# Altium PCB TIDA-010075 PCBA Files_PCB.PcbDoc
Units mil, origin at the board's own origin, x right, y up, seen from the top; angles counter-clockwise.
Board outline 1182.08 x 709 mil, 2 copper layers (Top Layer, Bottom Layer), stack 62 mil thick; 32 components, 16 nets, 78 pads, 87 vias.
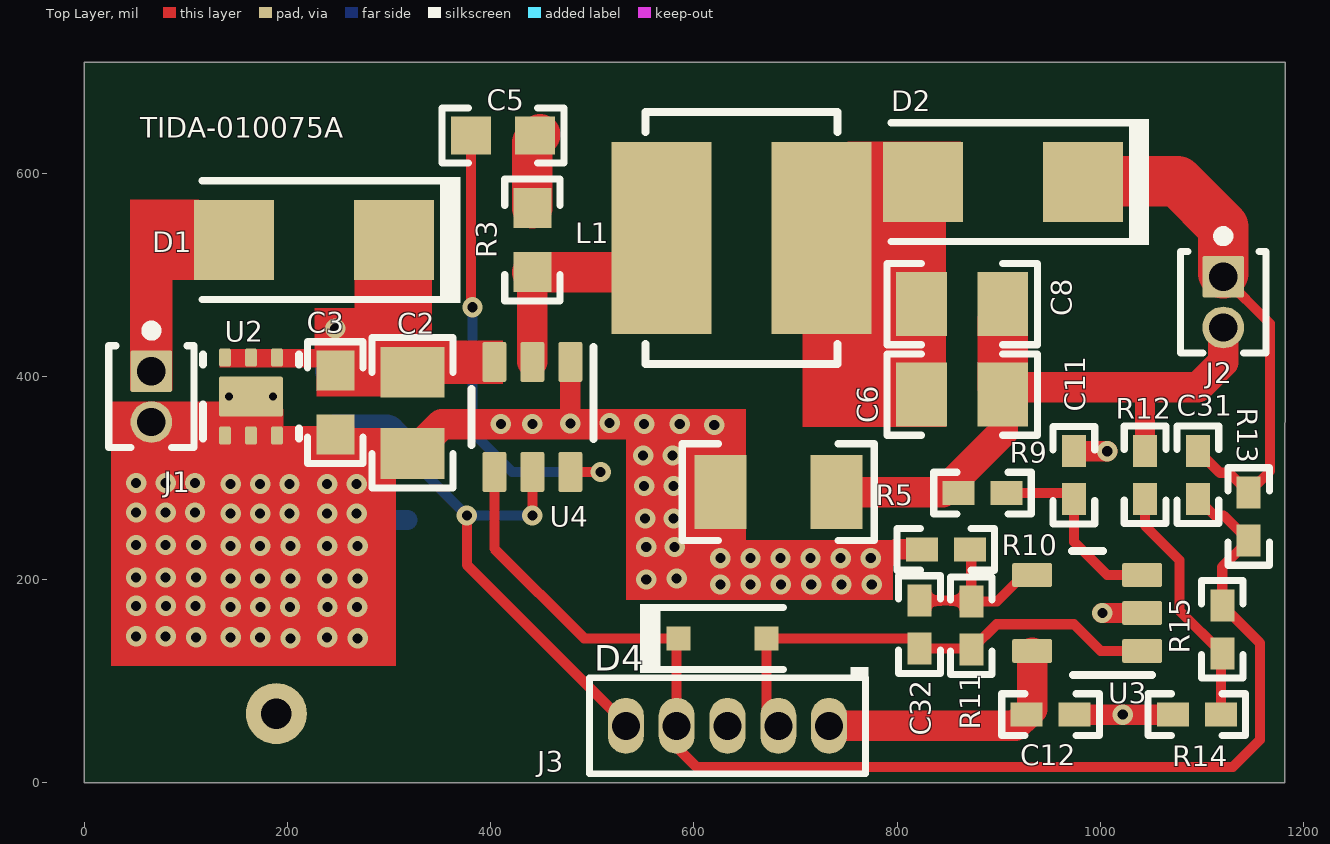
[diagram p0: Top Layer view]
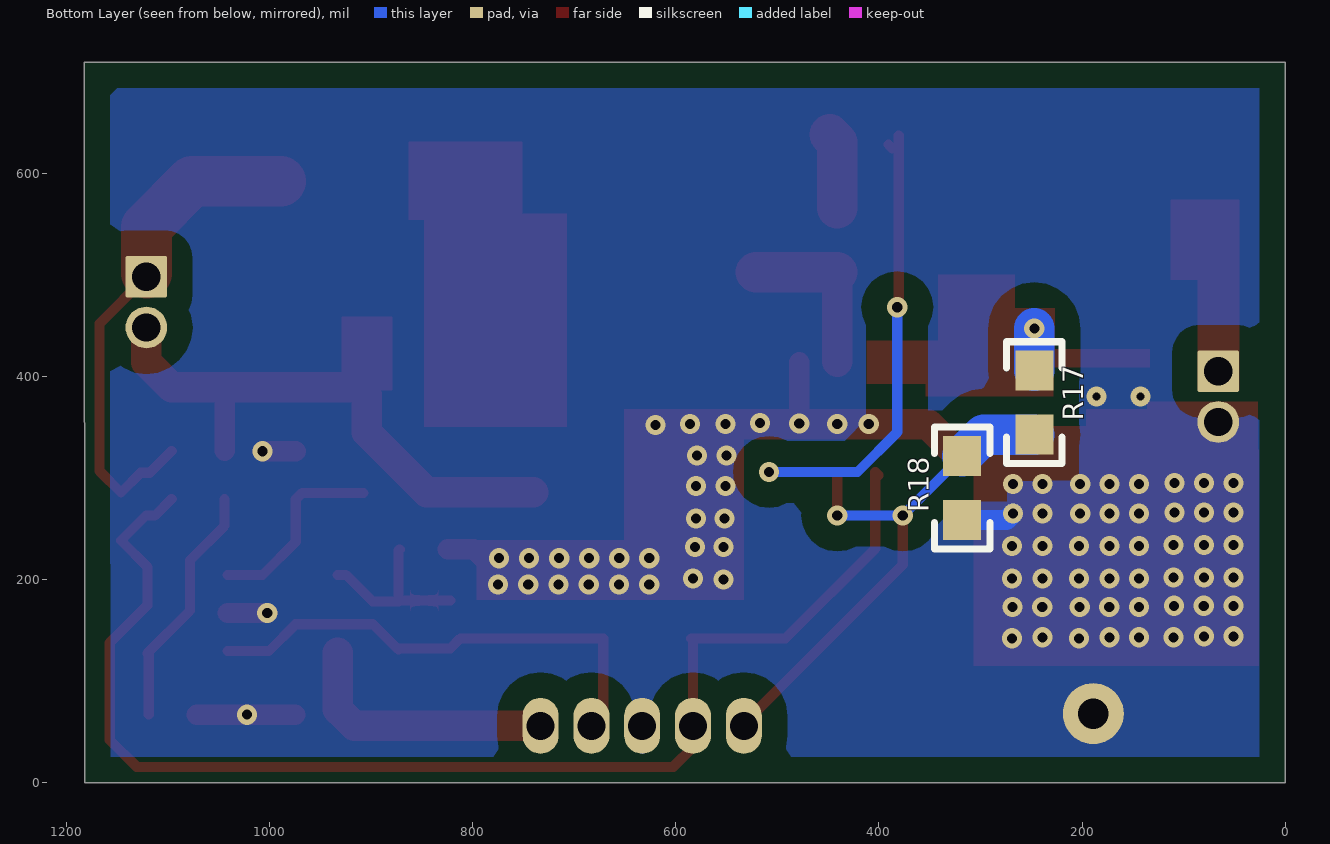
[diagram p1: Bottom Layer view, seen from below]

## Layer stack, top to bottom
Top Solder: solder mask 0.4, Solder Resist, Dk 3.5
Top Layer: signal copper 1.4
Dielectric1: core 59.2, FR-4, Dk 4.8
Bottom Layer: signal copper 1.4
Bottom Solder: solder mask 0.4, Solder Resist, Dk 3.5

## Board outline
0,0 1181.58,0 1182.08,709 0,709

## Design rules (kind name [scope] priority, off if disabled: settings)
AcuteAngle [All] p1: minimum=4.50000000000000E+0001 checktracksonly=FALSE
AssemblyTestPointUsage [All] p1: valid=2
BoardOutlineClearance BoardOutlineClearance_MountingHoles [OnCopper and InComponentClass('Mounting Holes')] p1: gap=40 ignorepadtopadclearanceinfootprint=FALSE
BoardOutlineClearance BoardOutlineClearance_Poly [OnCopper and IsPoly] p2: gap=25 ignorepadtopadclearanceinfootprint=FALSE
BoardOutlineClearance [OnCopper and Not InComponentClass('Logo') and not InComponentClass('FiducialMark') and not InRegion(1000,500,4000,800) and not InPoly] p3: gap=8 ignorepadtopadclearanceinfootprint=FALSE
Clearance Clearance_Keepouts [((IsTrack Or IsArc) And Not InPoly) And IsFree and IsKeepOut vs ((IsTrack Or IsArc) And Not InPoly) And IsFree and IsKeepOut] p1: gap=0 ignorepadtopadclearanceinfootprint=FALSE
Clearance Clearance_Poly [InPolygon] p2: gap=25 ignorepadtopadclearanceinfootprint=FALSE except(0: Arc-Hole Track-Hole SMDPad-Hole THPad-Hole Via-Hole Fill-Hole Poly-Hole Region-Hole Text-Hole)
Clearance Clearance_FiducialMark [IsKeepOut and InComponentClass('FiducialMark') vs IsPad and InComponentClass('FiducialMark')] p3: gap=0 ignorepadtopadclearanceinfootprint=FALSE
Clearance [All] p4: gap=7.87 ignorepadtopadclearanceinfootprint=FALSE except(0: Arc-Hole Track-Hole SMDPad-Hole THPad-Hole Via-Hole Fill-Hole Poly-Hole Region-Hole Text-Hole)
ComponentClearance ComponentClearance_MountingHoles_FiducialMarks [InComponentClass('Mounting Holes') vs InComponentClass('FiducialMark')] p1: gap=50 collisioncheckmode=3 verticalgap=10 showdistances=FALSE
ComponentClearance ComponentClearance_Shunt [InComponentClass('Header') vs InComponentClass('Shunt')] p2: gap=0 collisioncheckmode=3 verticalgap=0 showdistances=FALSE
ComponentClearance ComponentClearance_Logo [InComponentClass('Logo')] p3: gap=50 collisioncheckmode=3 verticalgap=10 showdistances=FALSE
ComponentClearance ComponentClearance_ScrewToNut [(HasFootprint('NY PMS 440 0025 PH')) vs (HasFootprint('Keystone_1902C'))] p4: gap=5 collisioncheckmode=3 verticalgap=10 showdistances=FALSE
ComponentClearance ComponentClearance_MountingHoles [InComponentClass('Mounting Holes')] p5: gap=250 collisioncheckmode=3 verticalgap=100000 showdistances=FALSE
ComponentClearance ComponentClearance_SmallPassives [HasFootprint('0201*') or HasFootprint('0402*') or HasFootprint('0508') or HasFootprint('0603*') or HasFootprint('0612') or HasFootprint('0805*') or HasFootprint('0815*') or HasFootprint('0830*') or HasFootprint('1206*') or HasFootprint('1210*') or HasFootprint('1808*') or HasFootprint('1812*') or HasFootprint('1825*') or HasFootprint('2010*') or HasFootprint('2220*') or HasFootprint('2225*') or HasFootprint('2512*') or HasFootprint('2728*') or HasFootprint('3518*') vs HasFootprint('0201*') or HasFootprint('0402*') or HasFootprint('0508') or HasFootprint('0603*') or HasFootprint('0612') or HasFootprint('0805*') or HasFootprint('0815*') or HasFootprint('0830*') or HasFootprint('1206*') or HasFootprint('1210*') or HasFootprint('1808*') or HasFootprint('1812*') or HasFootprint('1825*') or HasFootprint('2010*') or HasFootprint('2220*') or HasFootprint('2225*') or HasFootprint('2512*') or HasFootprint('2728*') or HasFootprint('3518*')] p6: gap=14.96 collisioncheckmode=3 verticalgap=10 showdistances=FALSE
ComponentClearance ComponentClearance_THtoSMT [IsThruComponent vs IsSMTComponent] p7: gap=10 collisioncheckmode=3 verticalgap=30 showdistances=FALSE
ComponentClearance ComponentClearance_THtoTH [IsThruComponent vs IsThruComponent] p8: gap=30 collisioncheckmode=3 verticalgap=30 showdistances=FALSE
ComponentClearance [All] p9: gap=10 collisioncheckmode=3 verticalgap=10 showdistances=FALSE
DiffPairsRouting [All] p1: maxlimit=100 minlimit=10 mostfreqgap=10 toplayer_minwidth=15 toplayer_maxwidth=15 toplayer_prefwidth=15 bottomlayer_minwidth=15 bottomlayer_maxwidth=15 bottomlayer_prefwidth=15 maxuncoupledlength=1000
FabricationTestPointUsage TestPointUsage [All] p1: valid=2 allowmultiple=FALSE
FabricationTestpoint Testpoint [All] p1: side=3 testpointundercomponent=TRUE minsize=40 maxsize=100 preferedsize=60 minholesize=0 maxholesize=40 preferedholesize=32 testpointgrid=1 allowsidetop=TRUE allowsidebottom=TRUE usegrid=TRUE gridtolerance=0.01
FanoutControl Fanout_LCC [IsLCC] p1: bgadir=Out bgaviamode=Centered fanoutstyle=Auto fanoutdirection=Alternating viagrid=1 // Fanout_LCC (Default Rule)
FanoutControl Fanout_BGA [IsBGA] p2: bgadir=Out bgaviamode=Centered fanoutstyle=Auto fanoutdirection=Alternating viagrid=1 // Fanout_BGA (Default Rule)
FanoutControl Fanout_Default [All] p4: bgadir=Out bgaviamode=Centered fanoutstyle=Auto fanoutdirection=Alternating viagrid=1 // Fanout_Default (Default Rule)
FanoutControl Fanout_Small [(CompPinCount < 5)] p5: bgadir=Out bgaviamode=Centered fanoutstyle=Auto fanoutdirection=OutThenIn viagrid=1 // Fanout_Small (Default Rule)
HoleSize [All] p1: absolutevalues=TRUE maxlimit=251 minlimit=7.87 maxpercent=80.000 minpercent=20.000
MinimumAnnularRing MinimumAnnularRing_ThermalPadVias [IsVia and InAnyComponent] p1: minimumring=5.91
MinimumAnnularRing [All] p2: minimumring=8
MinimumSolderMaskSliver MinimumSolderMaskSliver_Logo [InComponentClass('Logo') vs InComponentClass('Logo')] p1: minsoldermaskwidth=0.7
MinimumSolderMaskSliver [All] p2: minsoldermaskwidth=3.94
PlaneClearance [All] p1: clearance=10
PlaneConnect [All] p1: planeconnectstyle=Direct reliefexpansion=10 reliefentries=4 reliefconductorwidth=10 reliefairgap=10
PolygonConnect [All] p1: connectstyle=Direct reliefconductorwidth=10 reliefentries=4 polygonreliefangle="90 Angle" airgapwidth=10
RoutingVias ThermalPadVias [IsVia and InAnyComponent] p1: holewidth=7.87 width=19.68 viastyle="Through Hole" minholewidth=7.87 minwidth=19.68 maxholewidth=12.99 maxwidth=23.62
RoutingVias [All] p2: holewidth=16 width=34 viastyle="Through Hole" minholewidth=7.87 minwidth=20 maxholewidth=40 maxwidth=65
SilkToBoardRegionClearance [Not ((IsComment or IsDesignator) And (Hide <> 'False')) and not InRegion(1000,500,4000,800)] p1:
SilkToSilkClearance SilkToSilkClearance_Pb-FreeLogo [(HasFootprint('Pb-Free_Overlay_Medium') OR HasFootprint('Pb-Free_Overlay_Small')) vs (HasFootprint('Pb-Free_Overlay_Medium') OR HasFootprint('Pb-Free_Overlay_Small'))] p1: silktosilkclearance=0
SilkToSilkClearance [All] p2: silktosilkclearance=0
SilkToSolderMaskClearance SilkToComponentPadClearance [(IsPad or IsFill or IsRegion) and InAnycomponent] p1: minsilkscreentomaskgap=0 clearancetoexposedcopper=TRUE
SilkToSolderMaskClearance "Silk to Solder Mask Opening" [All] p2: minsilkscreentomaskgap=0 clearancetoexposedcopper=FALSE
SolderMaskExpansion [All] p1: expansion=1.97
Width [All] p1: maxlimit=100 minlimit=6 preferedwidth=10 checkconnectedcopper=TRUE
14 further rules are at their usual default settings.

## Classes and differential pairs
component class "TIDA-010075 PCBA Files_BlankSheet": C2 C3 C5 C6 C8 C11 C12 C31 C32 D1 D2 D4 J1 J2 J3 L1 R3 R5 R9 R10 R11 R12 R13 R14 R15 R17 R18 U2 U3 U4
component class Header: J1 J2 J3
component class Logo: Logo1
component class "TIDA-010075 PCBA Files_EVM_Hardware": Logo1 Logo3

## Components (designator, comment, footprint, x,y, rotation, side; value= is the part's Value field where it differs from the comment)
C2 "GRM21BR6YA106KE43L" 0805_HV 323,364 r270 top value=10uF
C3 "06035C104KAT2A" 0603 247,374 r270 top value=0.1uF
C5 "06035C104KAT2A" 0603 412,637 r180 top value=0.1uF
C6 "C2012X5R1V226M125AC" 0805_HV 864,382 r0 top value=22uF
C8 "C2012X5R1V226M125AC" 0805_HV 864,471 r0 top value=22uF
C11 "GRM155R71C104KA88D" 0402 974,302.63 r90 top value=0.1uF
C12 "GRM155R71C104KA88D" 0402 951,67 r180 top value=0.1uF
C31 "GRM1555C1E560JA01D" 0402 1096,303 r270 top value=56pF
C32 "885012005009" 0402 822,155.63 r90 top value=22pF
D1 "B340LA-13-F" SMA 226,534 r180 top value=40V
D2 "B340LA-13-F" SMA 904,591 r180 top value=40V
D4 "BAT54HT1G" SOD-323 628,142 r0 top value=30V
J1 "GRPB021VWVN-RC" Sullins_GRPB021VWVN-RC 66,380 r270 top
J2 "GRPB021VWVN-RC" Sullins_GRPB021VWVN-RC 1121,473 r270 top
J3 "GRPB051VWVN-RC" Sullins_GRPB051VWVN-RC 633,56 r180 top
L1 "THPC6045MF-220M" THPC6045MF 647,536 r0 top value=22uH
Logo1 "Texas Instruments" TI_Stacked_Overlay_Small 1175,871 r0 top
Logo3 "FCC disclaimer" FCC_disclaimer 2350,3380 r0 top
R3 "MCR03EZPJ000" 0603 441,534 r270 top value=0
R5 "CRM1206-FX-R100ELF" 1206 683,286 r0 top value=0.1
R9 "CRCW04021K50FKED" 0402 884,285 r180 top value=1.50k
R10 "CRCW04021K50FKED" 0402 848,229.63 r0 top value=1.50k
R11 "CRCW040216K5FKED" 0402 873,154.63 r270 top value=16.5k
R12 "CRCW04020000Z0ED" 0402 1044,303 r270 top value=0
R13 "CRCW0402100KFKED" 0402 1146,262 r90 top value=100k
R14 "CRCW04020000Z0ED" 0402 1095,67 r0 top value=0
R15 "CRCW04023K57FKED" 0402 1120,151 r90 top value=3.57k
R17 "CRCW06031K00FKEA" 0603 247,374 r90 bottom value=1.00k
R18 "CRCW06031K00FKEA" 0603 318,290 r90 bottom value=1.00k
U2 "TVS3300DRVR" DRV0006A 164,380 r90 top
U3 "TLV9001IDBVR" DBV0005A_N 987,167 r180 top
U4 "TPS54202HDDCR" DDC0006A_N 441,360 r270 top

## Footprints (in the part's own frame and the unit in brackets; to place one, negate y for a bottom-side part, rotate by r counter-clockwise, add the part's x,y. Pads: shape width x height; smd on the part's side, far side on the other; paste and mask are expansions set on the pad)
0402 [mm] "0402 from SM-752 data"
  rect 0.8x0.6 smd: 1(-0.6,0) 2(0.6,0)
  silkscreen extent -1.22,-0.52 1.22,0.52, body extent -0.55,-0.3 0.55,0.3, height 0.6
0603 [mm] "0603 from SM-752 data"
  rect 1x0.95 smd: 1(-0.8,0) 2(0.8,0)
  silkscreen extent -1.52,-0.69 1.52,0.69, body extent -0.87,-0.47 0.87,0.47, height 1
0805_HV [mil] "0805 with 30mil clearance between pads"
  rect 50x63 smd: 1(-40,0) 2(40,0)
  silkscreen extent -74,-40 74,40, body extent -43,-29 43,29, height 57
1206 [mm] "1206 from SM-752 data"
  rect 1.3x1.85 smd: 1(-1.45,0) 2(1.45,0)
  silkscreen extent -2.4,-1.21 2.4,1.21, body extent -1.7,-0.9 1.7,0.9, height 1.35
DBV0005A_N [mm] "SOT23, 5-Leads, Body 2.9x1.6mm, Pitch 0.95mm, Lead Span 2.8mm, IPC Medium Density"
  rrect17% 1x0.6 smd: 1(-1.375,0.95) 2(-1.375,0) 3(-1.375,-0.95) 4(1.375,-0.95) 5(1.375,0.95)
  silkscreen extent -1.63,-1.55 0.38,1.55, body extent -1.42,-1.46 1.42,1.46, height 1.09
DDC0006A_N [mm]
  rrect17% 1x0.6 smd: 1(-1.375,0.95) 2(-1.375,0) 3(-1.375,-0.95) 4(1.375,-0.95) 5(1.375,0) 6(1.375,0.95)
  silkscreen extent -1.75,-1.52 0.7,1.53, body extent -1.43,-1.48 1.43,1.49, height 0.92
DRV0006A [mm] "SON, 6-Leads, Body 2x2mm, Pitch 0.65mm, Thermal Pad 1.6x1mm, TI Recommended"
  rrect33% 0.45x0.3 smd: 1(-0.975,0.65) 2(-0.975,0) 3(-0.975,-0.65) 4(0.975,-0.65) 5(0.975,0) 6(0.975,0.65)
  rrect14% 1x0.7 on Top Paste: 7(0,0.45) 7(0,-0.45)
  rrect10% 1x1.6 smd paste-0.5: 7(0,0)
  silkscreen extent -1.05,-1.2 1.05,1.2, body extent -1.05,-1.05 1.05,1.05, height 0.81
FCC_disclaimer [mil]
SMA [mm] "Molded Diode, 2-Leads, Body 4.3x2.6mm, IPC Medium Density, based on OnSemi component dimensions and land pattern"
  rect 2x2 smd: 1(-2,0) 2(2,0)
  silkscreen extent -3.66,-1.57 2.79,1.57, body extent -2.6,-1.3 2.6,1.3, height 2.42
SOD-323 [mm] "NXP recommended land pattern"
  rect 0.6x0.6 smd paste-0.05: 1(-1.1,0) 2(1.1,0)
  silkscreen extent -2.06,-0.86 1.53,0.86, body extent -1.3,-0.67 1.3,0.68, height 1.1
Sullins_GRPB021VWVN-RC [mil] "Sullins"
  rrect10% 41x41 hole 28: 1(-25,0)
  round 41 hole 28: 2(25,0)
  silkscreen extent -70,-42 50,42, body extent -50,-42 50,42, height 157
Sullins_GRPB051VWVN-RC [mm] "SULLINS"
  oval 0.9x1.4 hole 0.7: 1(-2.54,0) 2(-1.27,0) 3(0,0) 4(1.27,0) 5(2.54,0)
  silkscreen extent -3.52,-1.47 3.45,1.2, body extent -3.42,-1.17 3.42,1.17, height 4.2
THPC6045MF [mm] "SMD, 2-Leads, Body 6x6mm"
  rect 2.5x4.8 smd: 1(-2,0) 2(2,0)
  silkscreen extent -2.4,-3.15 2.4,3.15, body extent -3.15,-3.15 3.15,3.15, height 4.5
TI_Stacked_Overlay_Small [mil]
  silkscreen extent -418,-98 418,98

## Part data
C2: "CAP, CERM, 10 µF, 35 V,+/- 10%, X5R, 0805", Cap_Case=0805, Manufacturer=MuRata, Supplier Part Number 1=490-10514-1-ND, TempCo=X5R, Tolerance_%=10, Value2=35V, ValueDisplayed=10µF
C3 C5: "CAP, CERM, 0.1 µF, 50 V,+/- 10%, X7R, 0603", Cap_Case=0603, Manufacturer=AVX, Supplier Part Number 1=478-5052-1-ND, TempCo=X7R, Tolerance_%=10, Value2=50V, ValueDisplayed=0.1µF
C6 C8: "CAP, CERM, 22 µF, 35 V,+/- 20%, X5R, 0805", Cap_Case=0805, Manufacturer=TDK, Supplier Part Number 1=445-14428-1-ND, TempCo=X5R, Tolerance_%=20, Value1="0.00205 ohm", Value2=35V, ValueDisplayed=22µF
C11 C12: "CAP, CERM, 0.1 µF, 16 V,+/- 10%, X7R, 0402", Cap_Case=0402, Manufacturer=MuRata, Supplier Part Number 1=490-3261-1-ND, TempCo=X7R, Tolerance_%=10, Value2=16V, ValueDisplayed=0.1µF
C31: "CAP, CERM, 56 pF, 25 V,+/- 5%, C0G/NP0, 0402", Cap_Case=0402, Manufacturer=MuRata, TempCo=C0G/NP0, Tolerance_%=5, Value2=25V, ValueDisplayed=56pF
C32: "CAP, CERM, 22 pF, 10 V,+/- 5%, C0G/NP0, 0402", Cap_Case=0402, Manufacturer="Wurth Elektronik", Supplier Part Number 1=732-7427-1-ND, TempCo=C0G/NP0, Tolerance_%=5, Value2=10V, ValueDisplayed=DNP
D1 D2: library part CMP-0028413-2, "Diode, Schottky, 40 V, 3 A, SMA", Manufacturer="Diodes Inc.", Value1=3A, Value2=0.45V
D4: library part CMP-0028455-2, "Diode, Schottky, 30 V, 0.2 A, SOD-323", Manufacturer="ON Semiconductor", Value1=0.2A, Value2=0.35V
J1 J2: "Header, 50mil, 2x1, Gold, TH", Manufacturer="Sullins Connector Solutions", Supplier Part Number 1=S9014E-02-ND
J3: "Header, 50mil, 5x1, Gold, TH", Manufacturer="Sullins Connector Solutions", Supplier Part Number 1=S9014E-05-ND
L1: "Inductor, Ferrite, 22 µH, 1.9 A, 0.096 ohm, SMD", Manufacturer=Tai-Tech, Value1="0.096 ohm", Value2=1.9A, ValueDisplayed=22µH
Logo1: library part CMP-0074838-1, "Texas Instrument Corporate Signature"
Logo3: library part CMP-0074847-1, "FCC_disclaimer"
R3: library part CMP-0025883-3, "RES, 0, 5%, 0.1 W, 0603", Manufacturer=Rohm, Power_W=100mW, Supplier Part Number 1=RHM0.0GCT-ND, TempCo="400 ppm/C", Tolerance_%=5%, Value2=0.1W, Value_Code=0000, ValueDisplayed=0
R5: "RES, 0.1, 1%, 0.5 W, 1206", Manufacturer=Bourns, Power_W=0.5, Supplier Part Number 1=652-CRM1206FXR100ELF, TempCo="150 ppm/C", Tolerance_%=1, Value1=1%, Value2=0.5W, Value_Code=R100, ValueDisplayed=0.1
R9 R10: "RES, 1.50 k, 1%, 0.063 W, 0402", Manufacturer=Vishay-Dale, Power_W=0.063, Supplier Part Number 1=541-1.50KLCT-ND, TempCo="100 ppm/C", Tolerance_%=1, Value1=1%, Value2=0.063W, Value_Code=1k50, ValueDisplayed=1.50k
R11: "RES, 16.5 k, 1%, 0.063 W, 0402", Manufacturer=Vishay-Dale, Power_W=0.063, Supplier Part Number 1=541-16.5KLCT-ND, TempCo="100 ppm/C", Tolerance_%=1, Value1=1%, Value2=0.063W, Value_Code=16k5, ValueDisplayed=16.5k
R12 R14: "RES, 0, 5%, 0.063 W, 0402", Manufacturer=Vishay-Dale, Power_W=0.063, Supplier Part Number 1=541-0.0JCT-ND, TempCo="200 ppm/C", Tolerance_%=5, Value1=5%, Value2=0.063W, Value_Code=0000, ValueDisplayed=0
R13: "RES, 100 k, 1%, 0.063 W, 0402", Manufacturer=Vishay-Dale, Power_W=0.063, Supplier Part Number 1=541-100KLCT-ND, TempCo="100 ppm/C", Tolerance_%=1, Value1=1%, Value2=0.063W, Value_Code=100k
R15: "RES, 3.57 k, 1%, 0.063 W, 0402", Manufacturer=Vishay-Dale, Power_W=0.063, Supplier Part Number 1=541-3.57KLCT-ND, TempCo="100 ppm/C", Tolerance_%=1, Value1=1%, Value2=0.063W, Value_Code=3k57, ValueDisplayed=3.57k
R17: "RES, 1.00 k, 1%, 0.1 W, 0603", Manufacturer=Vishay-Dale, Power_W=0.1, Supplier Part Number 1=541-1.00KHCT-ND, TempCo="100 ppm/C", Tolerance_%=1, Value1=1%, Value2=0.1W, Value_Code=1k00, ValueDisplayed=511k,DNP
R18: "RES, 1.00 k, 1%, 0.1 W, 0603", Manufacturer=Vishay-Dale, Power_W=0.1, Supplier Part Number 1=541-1.00KHCT-ND, TempCo="100 ppm/C", Tolerance_%=1, Value1=1%, Value2=0.1W, Value_Code=1k00, ValueDisplayed=105k,DNP
U2: "33V Precision Surge Protection Clamp, DRV0006A (WSON-6)", Alternate Manufacturer="Texas Instruments", Alternate PartNumber=TVS3300DRVT
U3: library part CMP-0081550-1, "Low-Power, Rail-to-Rail In and Out, 1-MHz Operational Amplifier, DBV0005A (SOT-23-5)", Alternate Manufacturer="Texas Instruments", Alternate PartNumber=TLV9001IDBVT
U4: library part CMP-0074516-2, "4.5-V TO 28-V INPUT, 2-A OUTPUT, EMI FRIENDLY SYNCHRONUOUS STEP-DOWN CONVERTOR, DDC0006A (SOT-23-T-6)", Alternate Manufacturer="Texas Instruments", Alternate PartNumber=TPS54202HDDCT

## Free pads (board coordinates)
  round 60 hole 30: 1(189,68)

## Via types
v1: diameter 20, hole 10, Top Layer to Bottom Layer, 85 vias
v2: diameter 19.68, hole 7.87, Top Layer to Bottom Layer, 2 vias

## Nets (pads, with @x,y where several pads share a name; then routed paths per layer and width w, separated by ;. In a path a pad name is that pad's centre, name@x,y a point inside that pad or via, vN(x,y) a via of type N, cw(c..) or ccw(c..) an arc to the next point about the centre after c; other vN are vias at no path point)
EN: J3.5 R17.1 R18.2 U4.5 | length 541.6
  Top Layer w10: v1(376.5,263) 376.5,214.5 533,58 J3.5 ; v1(441,263) U4.5
  Bottom Layer w10: R18.2 v1(376.5,263) v1(441,263)
  Bottom Layer w40: R17.1 296.99,342.5 R18.2
GND: C2.2 C3.2 C11.2 C12.1 J1.2 J3.3 pad.1 R5.1 R10.1 R14.1 R18.1 U2.1 U2.2 U2.3 U2.7@164,380 U3.2 U4.1 | length 832.5
  Top Layer w20: U4.1 v1(478.4,353.6) v1@479,353 ; 625,211 780,211 798.63,229.63 R10.1 ; C11.2 v1(1006.75,326.25) ; C12.1 v1(1022,67) R14.1 ; v1(1002,167) U3.2
  Top Layer w30: C2.2 352,353 479,353 558.91,353 R5.1
  Bottom Layer w20: v1(268,265) 274.5,258.5 R18.1
  other v1: 203,142 269,142 110,143 144,143 173,143 239,143 51,144 80,144 144,173 173.25,173 202.5,173 239.25,173 268.5,173 51,174 80.25,174 109.5,174 626,195 655.8,195 685.6,195 715.4,195 745.2,195 775,195 553,200 144,201 173,201 203,201 239,201 269,201 583,201 51,202 80,202 110,202 626,221 655.6,221 685.2,221 714.8,221 744.4,221 774,221 553,232 581,232 144,233 173,233 203,233 239,233 269,233 51,234 80,234 110,234 552,260 580,260 144,265 173,265 202,265 239,265 51,266 80,266 109,266 551,292 580,292 144,294 173,294 202,294 239,294 268,294 51,295 80,295 109,295 550,322 579,322 620,352 410,353 441,353 551,353 586,353 517,354
  other v2: 142.35,380 185.65,380
I_BAT: C32.1 D4.2 J3.2 R11.2 U3.1 | length 487.1
  Top Layer w10: J3.2 671.31,67.69 D4.2 812.01,142 C32.1 R11.2@874,132.01 ; R11.2 R11.2@874,132.01 ; U3.1 1000.4,129.6 974,156 897.99,156 R11.2@874,132.01
NetC5_1: C5.1 R3.1 | length 75.6
  Top Layer w40: R3.1 441,630.5 C5.1@448.5,638
NetC5_2: C5.2 U4.6 | length 472.6
  Top Layer w10: C5.2 380.5,466.5 v1(382,467.99) ; C5.2@387,624.5 C5.2@390.5,628 ; U4.6 v1(508.13,305.87)
  Bottom Layer w10: v1(382,467.99) 382,345 421.13,305.87 v1(508.13,305.87)
NetC6_1: C6.1 C8.1 D2.2 L1.2
NetC6_2: C6.2 C8.2 J2.2 R5.2 R9.2 R12.1 | length 552.4
  Top Layer w20: 1043,389 1044,388 R12.1
  Top Layer w30: R5.2 845,286 904,345 C6.2 911,389 1043,389 1096,389 1121,414 J2.2
NetC11_1: C11.1 R9.1 U3.3 | length 191.5
  Top Layer w10: R9.1 968.01,285 C11.1 974,237.07 1006.67,204.4 U3.3
NetC32_2: C32.2 R10.2 R11.1 U3.4 | length 174.1
  Top Layer w10: C32.2 872,179.25 R11.1 ; R10.2 873,228.25 R11.1 ; U3.4 924.4,204.4 898.25,178.25 R11.1
NetL1_1: L1.1 R3.2 U4.2 | length 168.4
  Top Layer w30: U4.2 R3.2
  Top Layer w40: R3.2 L1.1@520.98,502.5
NetR12_2: R12.2 R14.2 R15.1 | length 244.4
  Top Layer w10: R12.2 1044,253 1078,219 1078,169.38 R15.1 1118.62,126 R14.2
V_ADP: D1.2 J1.1
V_BAT: C31.2 D4.1 J3.4 R13.1 R15.2 U4.4 | length 1287.9
  Top Layer w10: U4.4@400.38,302.65 U4.4 403.6,230.4 492,142 D4.1 583,140.31 J3.4 583,35 602.43,15.57 1130.57,15.57 1157,42 1157,137.62 R15.2 1120,212.38 R13.1 1121.38,263 1112.38,263 C31.2
V_BIAS: C12.2 J3.1 U3.5 | length 262.3
  Top Layer w30: J3.1 916.38,56 C12.2 932.87,72.49 U3.5@932.87,128.13
V_SYS: C31.1 D2.1 J2.1 R13.2 | length 503.6
  Top Layer w10: C31.1 1117.62,305 1126.62,305 R13.2 1167,306.62 1167,452 J2.1
  Top Layer w50: D2.1@988.74,592 1076,592 1121,547 J2.1@1121,501.37
VIN_TPS: C2.1 C3.1 D1.1 R17.2 U2.4 U2.5 U2.6 U4.3 | length 41.5
  Bottom Layer w40: R17.2 v1(247,447)
pads on no net: U2.7@146.28,380 U2.7@181.72,380

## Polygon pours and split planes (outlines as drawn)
GND on Bottom Layer "BOTTOM_LAYER_GND_P000" (solid, remove dead copper, pour order 0): 0,709 1182.08,709 1182.08,0.5 1181.58,0 0,0

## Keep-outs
Keep-Out Layer:
  text ".Layer_Name" at 577,-858.49 h60

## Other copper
Top Layer:
  rectangle net GND: 27,322 135.93,375
  rectangle net V_ADP: 79,495 113,574
  rectangle net GND: 650,180 796,239
  rectangle net GND: 533,180 651,368
  rectangle net NetC6_2: 879,386.19 928.82,459
  rectangle net NetC6_1: 707,350 848,560
  rectangle net NetC6_1: 751,554 863,631
  rectangle net VIN_TPS: 226.73,426 271,467
  rectangle net VIN_TPS: 339,392.61 412.06,435
  rectangle net V_ADP: 45,386 86.54,574
  rectangle net GND: 132,331 196,368
  rectangle net VIN_TPS: 266,421 342,500
  rectangle net VIN_TPS: 228.32,380 354,427
  rectangle net VIN_TPS: 133,408.45 265.7,427
  rectangle net GND: 131,322 266,350.94
  rectangle net GND: 26,115 307,328
  rectangle net GND: 211,298 295,349
  text ".Layer_Name" at 577,-858.49 h60
Bottom Layer:
  text ".Layer_Name" at 577,-858.49 h60

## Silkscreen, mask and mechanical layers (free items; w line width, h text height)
Top Overlay:
  text "TIDA-010075A" at 55,635 h20
  text ".Layer_Name" at 577,-858.49 h60
Bottom Overlay:
  text ".Layer_Name" at 577,-858.49 h60
Top Paste:
  text ".Layer_Name" at 577,-858.49 h60
Bottom Paste:
  text ".Layer_Name" at 577,-858.49 h60
Top Solder:
  text ".Layer_Name" at 577,-858.49 h60
  text ".Layer_Name" at 577,-858.49 h60
Bottom Solder:
  text ".Layer_Name" at 577,-858.49 h60
Drill Guide:
  text ".Layer_Name" at 577,-858.49 h60
M1 Board Outline:
  the board outline again, w10
  text ".Layer_Name" at 577,-858.49 h60
M2 Board Dimensions:
  rectangle: 0,-275 125,-150
  rectangle: 125,-400 500,-275
  lines w7: 0,-275 1000,-275 ; 125,-400 125,-150 ; 250,-400 250,-150 ; 500,-400 500,-150 ; 750,-400 750,-150 ; 0,-400 1000,-400 1000,-150 0,-150 0,-400
  text ".Layer_Name" at 577,-858.49 h60
M3 3D STEP Top:
  text ".Layer_Name" at 577,-858.49 h60
M4 3D STEP Bottom:
  text ".Layer_Name" at 577,-858.49 h60
M5 Assembly Top:
  lines w10: -292,-930.17 6308,-930.17 ; -292,-726.83 6310,-726.83 ; -292,-523.5 -292,-1133.5 3713,-1133.5 6310,-1133.5 6310,-523.5 -291.5,-523.5 -291.5,-1133.5 1284,-1133.5 ; 2173,-1133.5 2173,-523.5 ; 3440,-726.83 3440,-523.5 ; 4280,-726.83 4280,-523.5 ; 4902,-1140 4902,-937.17
  text "COMPONENTS MARKED 'DNP' SHOULD NOT BE POPULATED." at 1153.5,-318.5 h60
  text "ASSEMBLY VARIANT:" at 1153,-434 h60
  text ".VariantName" at 2189,-434 h60
  text "PCB VIEWED FROM TOP SIDE" at -228.5,-655.67 h60
  text "BOARD #:" at 2248,-655.67 h60
  text ".PRJ_Number" at 2793.5,-655.67 h60
  text "REV:" at 3638,-655.67 h60
  text ".PCB_Rev" at 3929.5,-655.67 h60
  text "SVN REV:" at 4476,-655.67 h60
  text ".VersionControl_RevNumber" at 4982,-655.67 h60
  text "TID #:" at 2248,-859 h60
  text ".TID" at 2793.5,-859 h60
  text "PLOT NAME =" at -228.5,-1064.34 h60
  text ".plot_File_Name" at 577,-1064.34 h60
  text "GENERATED    :" at 2250,-1064.34 h60
  text ".Print_Date" at 3119.5,-1064.34 h60
  text ".Print_Time" at 3848.5,-1064.34 h60
  text "TEXAS INSTRUMENTS" at 5113,-1064.34 h60
M6 Assembly Bottom:
  lines w10: -292.5,-727.33 6309.5,-727.33 ; -290.5,-930.67 6309.5,-930.67 ; 1115.5,-1140.5 1115.5,-937.67 ; 1737.5,-727.33 1737.5,-524 ; 2577.5,-727.33 2577.5,-524 ; 3844.5,-1134 3844.5,-524 ; 4733.5,-1134 6309,-1134 6309,-524 -292.5,-524 -292.5,-1134 2304.5,-1134 6309.5,-1134 6309.5,-524
  text "COMPONENTS MARKED 'DNP' SHOULD NOT BE POPULATED." at 6102,-318 h60
  text ".VariantName" at 5058,-434 h60
  text "ASSEMBLY VARIANT:" at 6097,-434 h60
  text ".VersionControl_RevNumber" at 1035.5,-656.17 h60
  text "SVN REV:" at 1541.5,-656.17 h60
  text ".PCB_Rev" at 2088,-656.17 h60
  text "REV:" at 2379.5,-656.17 h60
  text ".PRJ_Number" at 3224,-656.17 h60
  text "BOARD #:" at 3769.5,-656.17 h60
  text "PCB VIEWED FROM BOTTOM SIDE" at 6246,-656.17 h60
  text ".TID" at 3224,-859.5 h60
  text "TID #:" at 3769.5,-859.5 h60
  text "TEXAS INSTRUMENTS" at 904.5,-1064.84 h60
  text ".Print_Time" at 2169,-1064.84 h60
  text ".Print_Date" at 2898,-1064.84 h60
  text "GENERATED    :" at 3767.5,-1064.84 h60
  text ".plot_File_Name" at 5440.5,-1064.84 h60
  text "PLOT NAME =" at 6246,-1064.84 h60
M9 Title Sheet:
  drawing of 57 lines, arcs and shapes, not listed
  text "1" at 739.84,8036.5 h70
  text "2" at 3235.5,8036.5 h70
  text "3" at 5724.84,8036.5 h70
  text "4" at 8231.51,8036.5 h70
  text "5" at 10730.5,8036.5 h70
  text "6" at 13235.5,8036.5 h70
  text "A" at -416.5,6893.5 h70
  text "A" at 14383.5,6893.5 h70
  text "B" at -416.5,4513.5 h70
  text "B" at 14383.5,4513.5 h70
  text "C" at -416.5,2138.5 h70
  text "C" at 14383.5,2138.5 h70
  text "PROJECT TITLE:" at 11343.5,277.5 h45
  text ".PRJ_Title" at 11393.5,144.17 h70
  text "DESIGNED FOR:" at 11343.5,-23.5 h45
  text ".PRJ_Customer" at 11393.5,-163.5 h70
  text "D" at -416.5,-231.5 h70
  text "D" at 14383.5,-231.5 h70
  text "FILE NAME:" at 11343.5,-323.5 h45
  text ".PCB_File_Name_No_Path" at 11393.5,-443.5 h70
  text "Texas Instruments (TI) and/or its licensors do not warrant the accuracy or completeness of this specification" at 6374,-605.34 h45
  text "ENGINEER:" at 11343.5,-613.5 h45
  text "LAYOUT BY:" at 12848.5,-613.5 h45
  text "or any information contained therein. TI and/or its licensors do not warrant that this design will meet" at 6329.01,-718 h45
  text ".PRJ_Engineer" at 11393.5,-768.49 h70
  text ".PCB_Layout" at 12899,-768.49 h70
  text "the specifications, will be suitable for your application or fit for any particular purpose, or will operate in" at 6329.01,-830.67 h45
  text ".Layer_Name" at 577,-858.49 h60
  text "ALTIUM DESIGNER VERSION:" at 12848.5,-923.5 h45
  text "an implementation. TI and/or its licensors do not warrant that the design is production worthy. You should" at 6329.01,-943.33 h45
  text "completely validate and test your design implementation to confirm the system functionality for your application." at 6374,-1056 h45
  text ".print_Scale" at 11393.5,-1056.83 h70
  text ".Application_BuildNumber" at 12899,-1056.83 h70
  text "1" at 739.84,-1263.5 h70
  text "2" at 3235.5,-1263.5 h70
  text "3" at 5724.84,-1263.5 h70
  text "4" at 8231.51,-1263.5 h70
  text "5" at 10730.5,-1263.5 h70
  text "6" at 13235.5,-1263.5 h70
M10 Fab Notes:
  drawing of 189 lines, arcs and shapes, not listed
  text "DESIGN INFORMATION" at 12382.02,6356.17 h60
  text "MIN. TRACK WIDTH:" at 11737.46,6224.05 h60
  text "8" at 12833.7,6224.05 h60
  text "MIL" at 12988.46,6224.05 h60
  text "MIN. CLEARANCE:" at 11737.46,6099.92 h60
  text "0.2" at 12773.7,6099.93 h60
  text "mm" at 12988.46,6099.92 h60
  text "MIN. VIA PAD SIZE:" at 11737.46,5975.8 h60
  text "24" at 12803.71,5975.8 h60
  text "MIL" at 12988.46,5975.8 h60
  text "0.05mm (2MIL)" at 12432.46,5845.9 h60
  text "MINIMUM ANNULAR RING" at 11408.23,5837.67 h60
  text "EXTERNAL" at 13140.46,5837.67 h60
  text "PER" at 11608.23,5727.55 h60
  text "IPC-D-275 CLASS 2 LEVEL C" at 11828.23,5727.54 h60
  text "MIL, HOLES" at 13316.46,5627.07 h60
  text "+/-" at 12924,5618.48 h60
  text "+/-" at 13778,5618.48 h60
  text "REGISTRATION TOLERANCES:" at 11408.23,5617.42 h60
  text "METAL" at 12608,5617.42 h60
  text "5" at 13184.2,5617.42 h60
  text "3" at 14017.2,5617.42 h60
  text "MIL" at 14133.46,5617.42 h60
  text "HOLE SIZE TOLERANCE (UNLESS OTHERWISE SPECIFIED):" at 11408.23,5519.1 h60
  text "+/-" at 13778,5516.23 h60
  text "3" at 14017.2,5515.17 h60
  text "MIL" at 14133.46,5515.17 h60
  text "MATERIAL:" at 11333.46,5377.52 h60
  text "FR-4 High Tg" at 12319.9,5249 h60
  text "X" at 12175.46,5241.01 h60
  text "FR-408" at 11754.46,5236.49 h60
  text "OTHER" at 13242.46,5236.49 h60
  text "62 MIL (1.6mm) +/-10%" at 12074.56,5093.46 h60
  text "X" at 11954.46,5091.01 h60
  text "THICKNESS:" at 11408.23,5085.24 h60
  text "OTHER" at 13359.46,5085.24 h60
  text "TOLERANCE:" at 11408.23,4946.92 h60
  text "X" at 12256.46,4946.92 h60
  text "ANSI IPC-6012 TYPE 3 CLASS 2" at 12434.48,4946.92 h60
  text "OTHER +/-" at 12434.46,4802.73 h60
  text "BOW & TWIST:" at 11408.23,4657.54 h60
  text "X" at 12256.46,4657.54 h60
  text "ANSI IPC-6012 TYPE 3 CLASS 2" at 12434.48,4657.54 h60
  text "OTHER +/-" at 12434.46,4510.85 h60
  text "DRILLING:" at 11333.46,4380.23 h60
  text "NC_DRILL FILES" at 13094.46,4275.04 h60
  text "REFERENCE:" at 11408.23,4271.1 h60
  text "X" at 12065.46,4271.01 h60
  text "AS SHOWN" at 12243.46,4271.1 h60
  text "X" at 12966.46,4271.1 h60
  text "OTHER" at 13392.46,4128.85 h60
  text "PTH COPPER THICKNESS:" at 11407.91,4125.32 h60
  text "X" at 12547.14,4125.32 h60
  text "20-30 um" at 12675.14,4125.32 h60
  text "BOARD FINISH:" at 11333.46,3977.73 h60
  text "SILKSCREEN:" at 11488.68,3867.6 h60
  text "X" at 12446.46,3867.6 h60
  text "TOP" at 12563.46,3867.6 h60
  text "X" at 12956.46,3867.6 h60
  text "BOTTOM" at 13074.46,3867.6 h60
  text "SILKSCREEN COLOR:" at 11488.68,3712.41 h60
  text "X" at 12445.46,3712.41 h60
  text "WHITE" at 12563.46,3712.41 h60
  text "OTHER" at 13074.46,3712.41 h60
  text "X" at 12576.46,3568.96 h60
  text "GREEN" at 12694.46,3568.96 h60
  text "OTHER" at 13312.46,3568.96 h60
  text "SOLDER RESIST COLOR:" at 11488.68,3562.1 h60
  text "X" at 12576.46,3414.71 h60
  text "MATTE" at 12694.46,3414.71 h60
  text "SEMI-GLOSS" at 13312,3414.07 h60
  text "IMMERSION GOLD (ENIG)" at 12394.46,3241.94 h60
  text "ENEPIG" at 13732,3234.72 h60
  text "SURFACE FINISH:" at 11333.46,3233.72 h60
  text "X" at 12216.46,3233.72 h60
  text "IMM. TIN/SILVER OR EQUIV" at 11663,3096.4 h60
  text "OTHER" at 13094.46,3092.47 h60
  text "ARRAY/PANEL:" at 11333.46,2937.09 h60
  text "CUT AND TRIM PER M1 BOARD OUTLINE" at 12394.46,2928.87 h60
  text "N.C. ROUTE" at 12394.46,2792.9 h60
  text "X" at 13082.46,2792.9 h60
  text "V. SCORE" at 13260.46,2792.9 h60
  text "CERTIFICATION:" at 11333.46,2663.77 h60
  text "MATERIALS AND WORKMANSHIP FOR ALL PCBS" at 12058.46,2663.77 h60
  text "TO MEET OR EXCEED THE REQUIREMENTS OF:" at 12058.46,2569.71 h60
  text "X" at 11695.97,2441.08 h60
  text "ANSI IPC-A-600F CLASS ->" at 11823.96,2441.08 h60
  text "X" at 13471.97,2441.08 h60
  text "2" at 13581.96,2441.08 h60
  text "1" at 13266.96,2439.58 h60
  text "3" at 13935.96,2439.58 h60
  text "X" at 12507.97,2293.39 h60
  text "RoHS" at 12635.96,2293.39 h60
  text "OTHER" at 13280.36,2293.39 h60
  text "PER ORDER" at 13677.42,2293.39 h60
  text "ALL BOARDS MUST MEET OR EXCEED UL94-V0 REQUIREMENTS." at 11361,2139.57 h60
  text "PCB MUST BEAR THE UL94V-0 UL REGISTERED MATERIAL ID NUMBER" at 11361,2023.5 h60
  text "ADDITIONAL REQUIREMENTS:" at 11333.46,1854.08 h60
  text "MICROSECTION:" at 11408.23,1746.95 h60
  text "YES" at 12313.96,1746.95 h60
  text "REQUIRED" at 13175.46,1602.62 h60
  text "BARE BOARD ELEC. TEST:" at 11408.23,1599.76 h60
  text "NONE" at 12713.96,1599.76 h60
  text "X" at 13057.46,1599.76 h60
  text "PER ORDER" at 13767.46,1599.76 h60
  text "XX MIL VIAS REQUIRE NON-CONDUCTIVE FILL AND PLANARIZE" at 11576.38,1394.82 h59
  text "XX MIL VIAS REQUIRE CONDUCTIVE FILL AND PLANARIZE" at 11584.38,1290.84 h60
  text "OUTER XX MIL TRACES REQUIRE 50 OHM SINGLE-ENDED IMPEDANCE" at 11583.39,1127.46 h58
  text "LAYER 2 & 3 (INNER LAYERS) XX MIL WIDE, XX MIL SPACE / TRACES REQUIRE 100 OHM DIFFERENTIAL IMPEDANCE" at 11575.39,891.74 h60
  text ".Layer_Name" at 577,-858.49 h60
M11 Gerber Information:
  lines w10: -292,-930.17 6308,-930.17 ; -292,-726.83 6310,-726.83 ; -292,-523.5 -292,-1133.5 3713,-1133.5 6310,-1133.5 6310,-523.5 -291.5,-523.5 -291.5,-1133.5 1284,-1133.5 ; 2173,-1133.5 2173,-523.5 ; 3440,-726.83 3440,-523.5 ; 4280,-726.83 4280,-523.5 ; 4902,-1140 4902,-937.17
  text "ALL ARTWORK VIEWED FROM TOP SIDE" at -228.5,-655.67 h60
  text "BOARD #:" at 2248,-655.67 h60
  text ".PRJ_Number" at 2793.5,-655.67 h60
  text "REV:" at 3638,-655.67 h60
  text ".PCB_Rev" at 3929.5,-655.67 h60
  text "SVN REV:" at 4476,-655.67 h60
  text ".VersionControl_RevNumber" at 4982,-655.67 h60
  text "LAYER NAME =" at -228.5,-858.49 h60
  text "TID #:" at 2248,-859 h60
  text ".TID" at 2793.5,-859 h60
  text "PLOT NAME =" at -228.5,-1064.34 h60
  text ".plot_File_Name" at 577,-1064.34 h60
  text "GENERATED    :" at 2250,-1064.34 h60
  text ".Print_Date" at 3119.5,-1064.34 h60
  text ".Print_Time" at 3848.5,-1064.34 h60
  text "TEXAS INSTRUMENTS" at 5113,-1064.34 h60
M12 Stackup:
  drawing of 191 lines, arcs and shapes, not listed
  text "Layer" at 9797.84,7830 h60
  text "Name" at 10207.76,7830 h60
  text "Material" at 11137.5,7830 h60
  text "Thickness" at 11997.27,7830 h60
  text "Constant" at 12647.1,7830 h60
  text "Board Layer Stack" at 13216.96,7830 h60
  text "1" at 9797.84,7710 h60
  text "Top Overlay" at 10207.76,7710 h60
  text "2" at 9797.84,7590 h60
  text "Top Solder" at 10207.76,7590 h60
  text "Solder Resist" at 11137.5,7590 h60
  text "0.40mil" at 11997.27,7590 h60
  text "3.5" at 12647.1,7590 h60
  text "3" at 9797.84,7470 h60
  text "Top Layer" at 10207.76,7470 h60
  text "Copper" at 11137.5,7470 h60
  text "1.40mil" at 11997.27,7470 h60
  text "4" at 9797.84,7350 h60
  text "Dielectric1" at 10207.76,7350 h60
  text "FR-4" at 11137.5,7350 h60
  text "59.20mil" at 11997.27,7350 h60
  text "4.8" at 12647.1,7350 h60
  text "5" at 9797.84,7230 h60
  text "Bottom Layer" at 10207.76,7230 h60
  text "Copper" at 11137.5,7230 h60
  text "1.40mil" at 11997.27,7230 h60
  text "6" at 9797.84,7110 h60
  text "Bottom Solder" at 10207.76,7110 h60
  text "Solder Resist" at 11137.5,7110 h60
  text "0.40mil" at 11997.27,7110 h60
  text "3.5" at 12647.1,7110 h60
  text "7" at 9797.84,6990 h60
  text "Bottom Overlay" at 10207.76,6990 h60
  text ".Layer_Name" at 577,-858.49 h60
M13 Component Bodies Top:
  text ".Layer_Name" at 577,-858.49 h60
M14 Component Bodies Bottom:
  text ".Layer_Name" at 577,-858.49 h60
M15 Courtyards Top:
  text ".Layer_Name" at 577,-858.49 h60
M16 Courtyards Bottom:
  text ".Layer_Name" at 577,-858.49 h60
Drill Drawing:
  circle w10: c5348.72,3005.27 r22.07
  lines w10: 5326.65,2928.02 5370.79,2928.02 5348.72,2883.88 5326.65,2928.02 ; 5326.65,3082.52 5370.79,3082.52 5370.79,3126.66 5326.65,3126.66 5326.65,3082.52 ; 5326.65,3192.87 5337.68,3192.87 5337.68,3181.84 5359.75,3181.84 5359.75,3192.87 5370.79,3192.87 5370.79,3214.94 5359.75,3214.94 5359.75,3225.98 5337.68,3225.98 5337.68,3214.94 5326.65,3214.94 5326.65,3192.87 ; 5326.65,3292.19 5337.68,3292.19 5348.72,3281.16 5359.75,3292.19 5370.79,3292.19 5359.75,3303.23 5370.79,3314.26 5359.75,3314.26 5348.72,3325.3 5337.68,3314.26 5326.65,3314.26 5337.68,3303.23 5326.65,3292.19
  lines w12: 5286,2854.08 8397.21,2854.08 ; 5286,3350.68 8397.21,3350.68 ; 5601.49,2754.76 5601.49,3450 ; 5918.58,2754.76 5918.58,3450 ; 6540.22,2754.76 6540.22,3450 ; 6784.41,2754.76 6784.41,3450 ; 7144.66,2754.76 7144.66,3450 ; 7853.12,2754.76 7853.12,3450 ; 5286,2754.76 8397.21,2754.76 8397.21,3450 5286,3450 5286,2754.76
  text "Symbol" at 5345.59,3380.48 h72
  text "Quantity" at 5631.28,3380.48 h72
  text "Finished Hole Size" at 5948.38,3380.48 h72
  text "Plated" at 6570.02,3380.48 h72
  text "Hole Type" at 6814.21,3380.48 h72
  text "Drill Layer Pair" at 7174.45,3380.48 h72
  text "Hole Tolerance" at 7882.92,3380.48 h72
  text "2" at 5631.28,3281.16 h60
  text "7.87mil (0.200mm)" at 5948.38,3281.16 h60
  text "PTH" at 6570.02,3281.16 h60
  text "Round" at 6814.21,3281.16 h60
  text "Top Layer - Bottom Layer" at 7174.45,3281.16 h60
  text "85" at 5631.28,3181.84 h60
  text "10.00mil (0.254mm)" at 5948.38,3181.84 h60
  text "PTH" at 6570.02,3181.84 h60
  text "Round" at 6814.21,3181.84 h60
  text "Top Layer - Bottom Layer" at 7174.45,3181.84 h60
  text "5" at 5631.28,3082.52 h60
  text "27.56mil (0.700mm)" at 5948.38,3082.52 h60
  text "PTH" at 6570.02,3082.52 h60
  text "Round" at 6814.21,3082.52 h60
  text "Top Layer - Bottom Layer" at 7174.45,3082.52 h60
  text "4" at 5631.28,2983.2 h60
  text "28.00mil (0.711mm)" at 5948.38,2983.2 h60
  text "PTH" at 6570.02,2983.2 h60
  text "Round" at 6814.21,2983.2 h60
  text "Top Layer - Bottom Layer" at 7174.45,2983.2 h60
  text "1" at 5631.28,2883.88 h60
  text "30.00mil (0.762mm)" at 5948.38,2883.88 h60
  text "PTH" at 6570.02,2883.88 h60
  text "Round" at 6814.21,2883.88 h60
  text "Top Layer - Bottom Layer" at 7174.45,2883.88 h60
  text "97 Total" at 5631.28,2784.56 h60
  text ".Layer_Name" at 577,-858.49 h60
M17 Embedded Cavity:
  text ".Layer_Name" at 577,-858.49 h60
M18 Embedded Assembly:
  text ".Layer_Name" at 577,-858.49 h60
M19 Embedded Keepout:
  text ".Layer_Name" at 577,-858.49 h60

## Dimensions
0,709 to 0,0 on M2 Board Dimensions
0,-400 to 1000,-400 on M2 Board Dimensions
0,0 to 1181.58,0 on M2 Board Dimensions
